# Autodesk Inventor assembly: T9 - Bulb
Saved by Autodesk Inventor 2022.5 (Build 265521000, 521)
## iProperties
Created: 2024-07
Part Number: T9 - Bulb
Document SubType Name: Assembly
Designer: AdminForWorker
Title: T9 - Bulb v3
Author: AdminForWorker
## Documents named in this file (2)
- c:\worker\convert-fusion-r03-cosv3\tmp\job-1\30\temp\files\365bae9e-e80c-4fba-9af5-331234e5ea32\T9 - Bulb v3.iam
- c:\worker\convert-fusion-r03-cosv3\tmp\job-1\30\temp\files\365bae9e-e80c-4fba-9af5-331234e5ea32\T9 - LED Bulb.iam
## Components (1 placed, 1 different names)
1. T9 - LED Bulb:1 [sub-assembly]
